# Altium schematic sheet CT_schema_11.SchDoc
size 387 x 278 mm
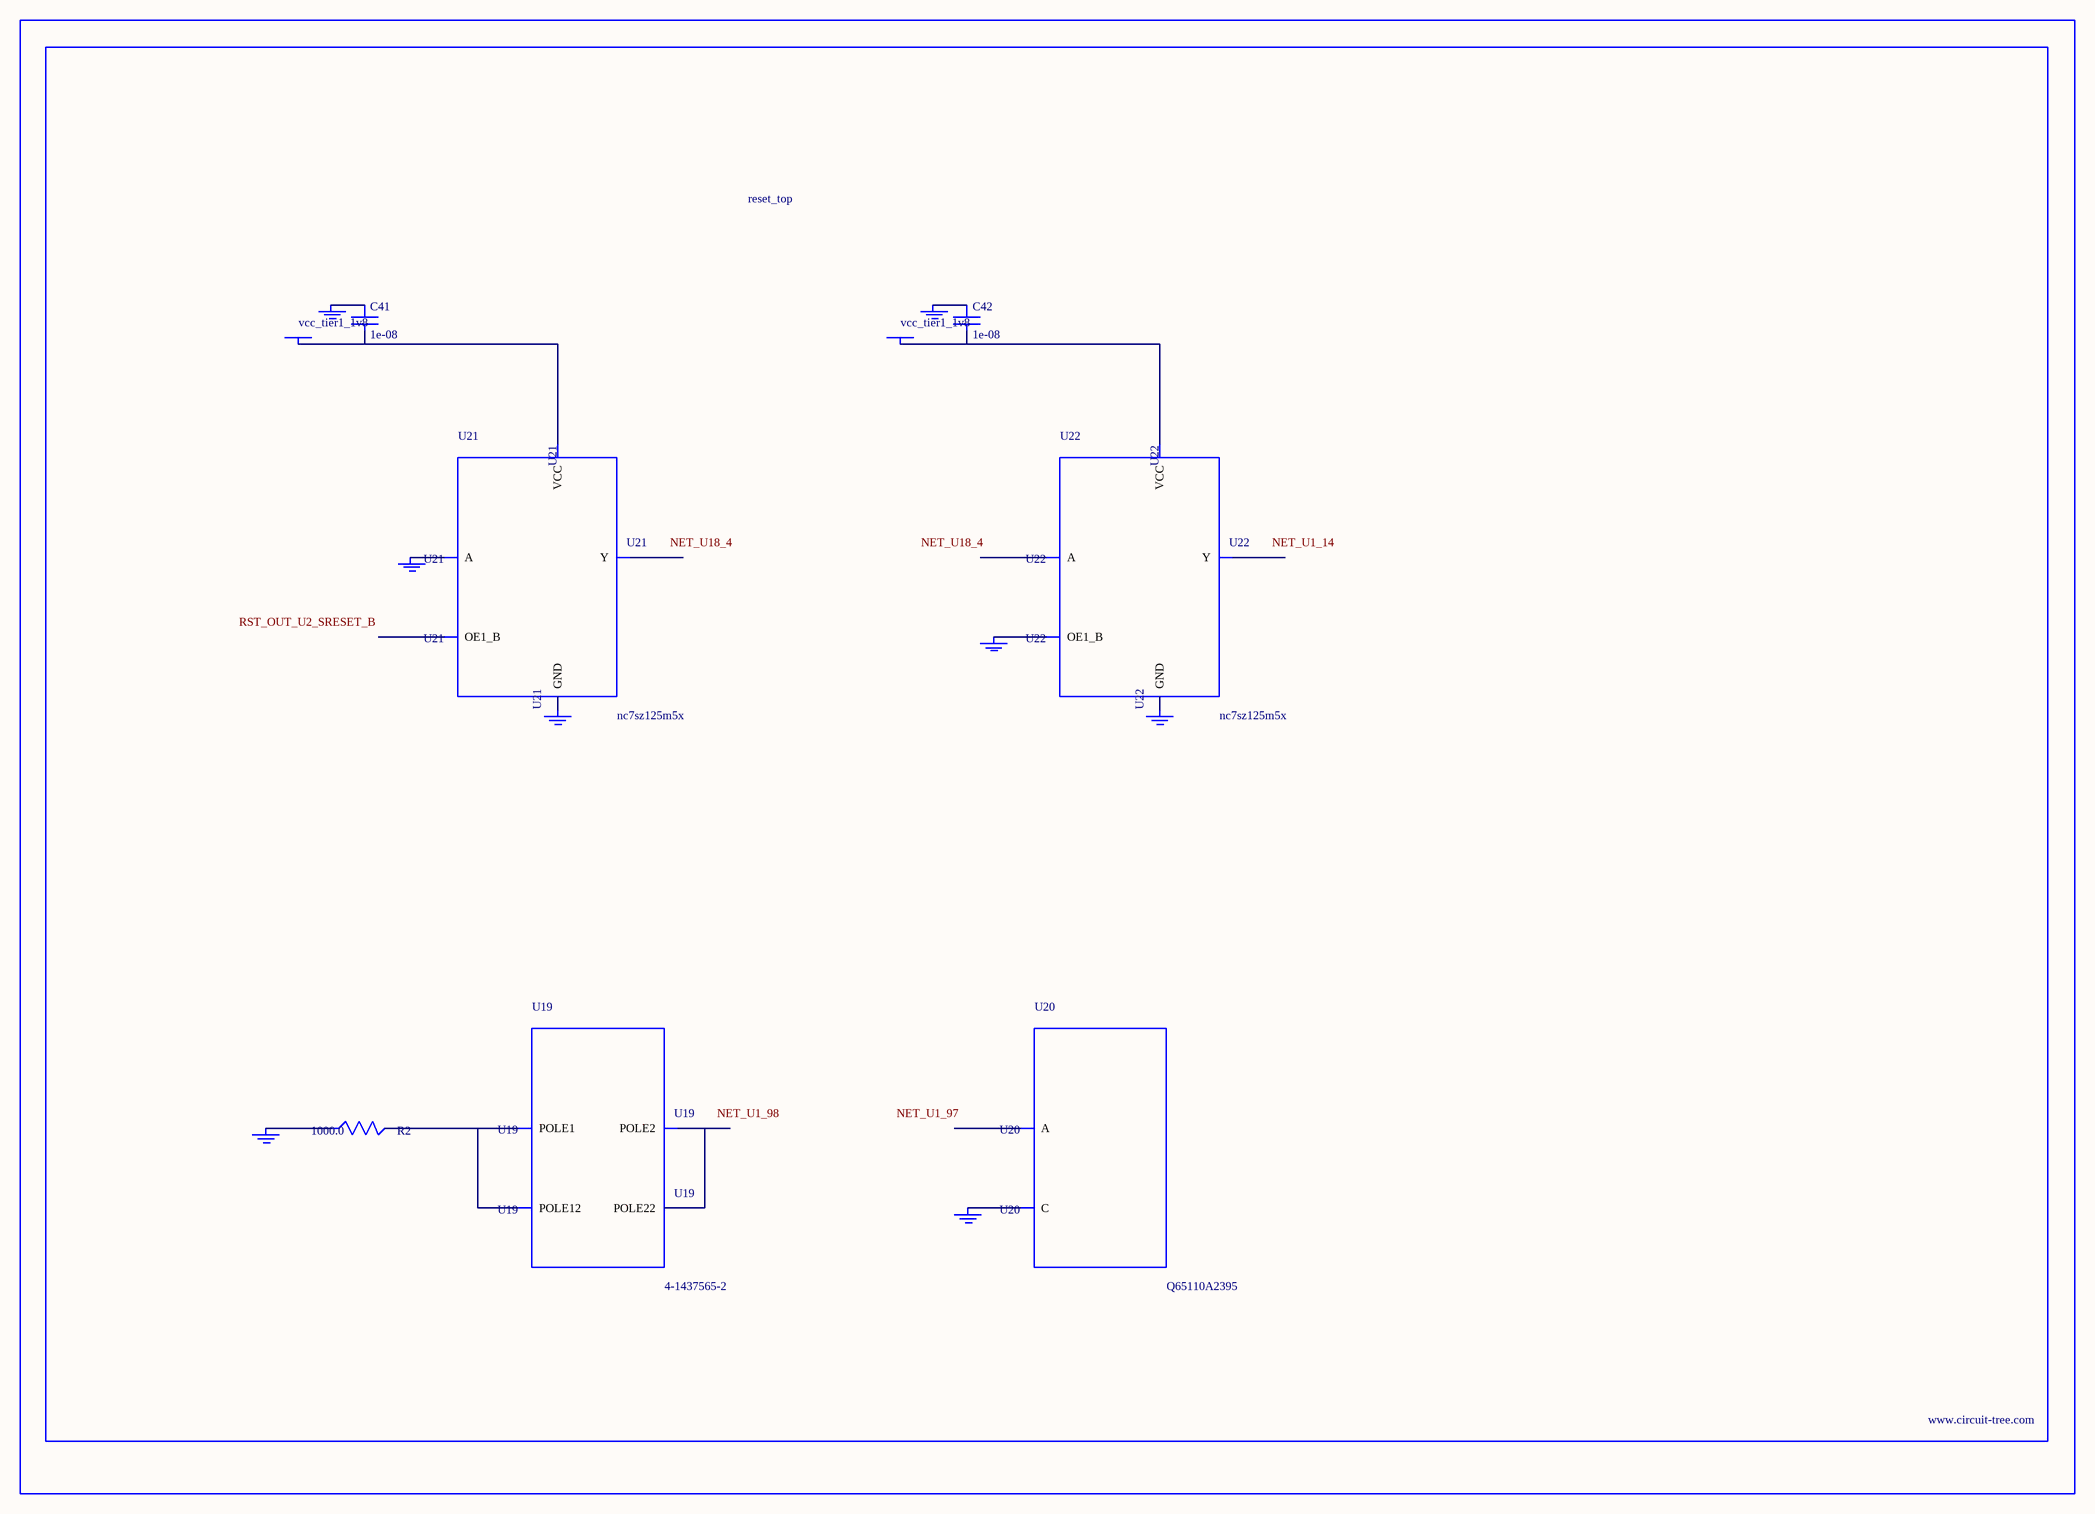
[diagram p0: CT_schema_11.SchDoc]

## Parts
BORDER10  (no value)
C41  1e-08  [C0402]
C42  1e-08  [C0402]
GND_INSTANCE_10_0  (no value)
GND_INSTANCE_10_1  (no value)
GND_INSTANCE_10_2  (no value)
GND_INSTANCE_10_3  (no value)
GND_INSTANCE_10_4  (no value)
GND_INSTANCE_10_5  (no value)
GND_INSTANCE_10_6  (no value)
GND_INSTANCE_10_7  (no value)
POWER_INSTANCE_10_0  vcc_tier1_1v8
POWER_INSTANCE_10_1  vcc_tier1_1v8
R2  1000.0  [R0603]
U19  4-1437565-2  [SW_4-1437565-2]
U20  Q65110A2395  [LGM67K-G1J2-24-Z]
U21  nc7sz125m5x  [NC7SZ125M5X]
U22  nc7sz125m5x  [NC7SZ125M5X]

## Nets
NetC41_1: C41.1 GND_INSTANCE_10_2.0(GND)
NetC41_2: C41.2 POWER_INSTANCE_10_0.0(PWR) U21.5(VCC)
NetC42_1: C42.1 GND_INSTANCE_10_5.0(GND)
NetC42_2: C42.2 POWER_INSTANCE_10_1.0(PWR) U22.5(VCC)
NetGND_INSTANCE_10_0_0: GND_INSTANCE_10_0.0(GND) R2.1
NetGND_INSTANCE_10_1_0: GND_INSTANCE_10_1.0(GND) U20.C
NetGND_INSTANCE_10_3_0: GND_INSTANCE_10_3.0(GND) U21.2(A)
NetGND_INSTANCE_10_4_0: GND_INSTANCE_10_4.0(GND) U21.3(GND)
NetGND_INSTANCE_10_6_0: GND_INSTANCE_10_6.0(GND) U22.1(OE1_B)
NetGND_INSTANCE_10_7_0: GND_INSTANCE_10_7.0(GND) U22.3(GND)
NetR2_2: R2.2 U19.1(POLE1) U19.2(POLE12)
NetU19_3: U19.3(POLE2) U19.4(POLE22)

Not connected (* = marked no-connect by the designer): U20 A; U21 1(OE1_B) 4(Y); U22 2(A) 4(Y)

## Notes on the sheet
- Labels drawn without touching a wire or pin: NET_U1_14, NET_U1_97, NET_U1_98, NET_U18_4, RST_OUT_U2_SRESET_B

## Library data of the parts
BORDER10 = BORDER_PAGE10
C41 C42 = C0402C103K3RAC
GND_INSTANCE_10_0-GND_INSTANCE_10_7 = GND
POWER_INSTANCE_10_0 POWER_INSTANCE_10_1 = PWR
R2 = RC0603JR-071KL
